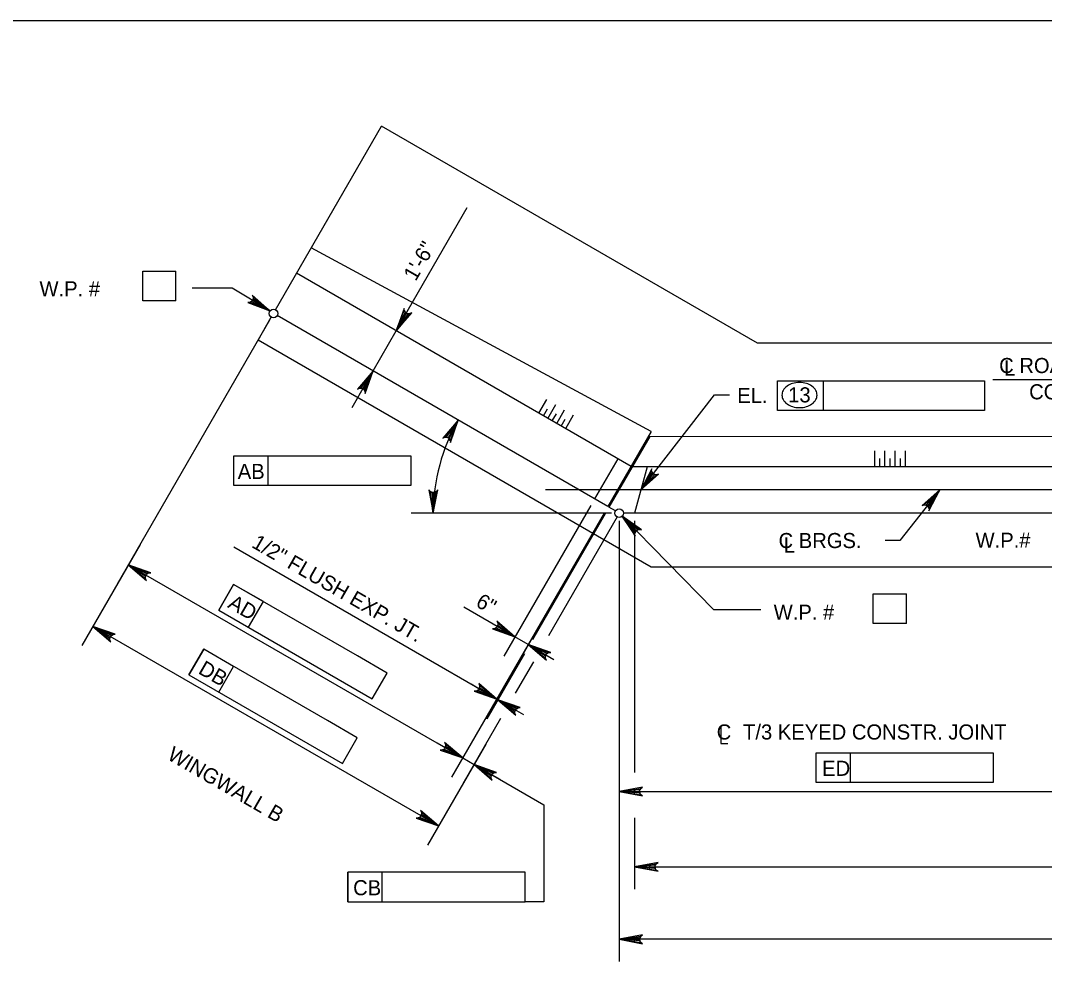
# Model space of a CAD drawing. Extents: x 638255 to 640306, y 296059 to 298435.
# Drawn here: x 638490.2 to 638693.7, y 297045.5 to 297232.5 of the extents above; entities that cross this region are included whole.
import ezdxf

# ---------------------------------------------------------------- set-up
doc = ezdxf.new("R2010")
doc.units = 0
for name, color, linetype in [('2', 7, 'Continuous'), ('Level 10', 7, 'Continuous'), ('Level 2', 7, 'Continuous'), ('Level 3', 7, 'Continuous')]:
    doc.layers.add(name, color=color, linetype=linetype)

msp = doc.modelspace()

# ---------------------------------------------------------------- linework, layer by layer
at = {"layer": '2'}
msp.add_line((638475.46, 297232.46), (639261.46, 297232.46), dxfattribs=at)
at = {"layer": 'Level 10'}
for p, q in [((638540.91, 297174.98), (638561.98, 297211.46)), ((638636.66, 297168.34), (638561.98, 297211.46)), ((638615.56, 297150.77), (638548, 297187.26)), ((638611.56, 297143.84), (638545.09, 297182.22)), ((638537.42, 297168.92), (638540.06, 297173.51)), ((638606.95, 297135.87), (638541.22, 297173.82)), ((638615.53, 297123.83), (638537.42, 297168.92)), ((638810.57, 297168.34), (638636.66, 297168.34)), ((638615.56, 297150.77), (638606.95, 297135.87)), ((638615.29, 297149.79), (638607.17, 297135.74)), ((638615.29, 297149.79), (638831.04, 297149.87)), ((638608.9, 297145.38), (638604.29, 297137.4)), ((638834.55, 297143.78), (638611.82, 297143.78)), ((638614.73, 297143.78), (638612.27, 297134.57)), ((638859.26, 297139.18), (638594.57, 297139.18)), ((638608.46, 297135), (638607.17, 297135.74)), ((638724.77, 297134.57), (638610.04, 297134.57)), ((638834.78, 297123.83), (638615.53, 297123.83))]:
    msp.add_line(p, q, dxfattribs=at)
at = {"layer": 'Level 2'}
for p, q in [((638593.24, 297154.42), (638594.82, 297157.15)), ((638594.13, 297153.91), (638594.94, 297155.31)), ((638595.01, 297153.39), (638596.59, 297156.12)), ((638596.79, 297152.37), (638598.36, 297155.1)), ((638595.9, 297152.88), (638596.71, 297154.28)), ((638597.67, 297151.86), (638598.48, 297153.26)), ((638598.56, 297151.35), (638600.13, 297154.08)), ((638659.97, 297143.78), (638659.97, 297146.94)), ((638662.02, 297143.78), (638662.02, 297146.94)), ((638664.06, 297143.78), (638664.06, 297146.94)), ((638666.11, 297143.78), (638666.11, 297146.94)), ((638660.99, 297143.78), (638660.99, 297145.4)), ((638663.04, 297143.78), (638663.04, 297145.4)), ((638665.09, 297143.78), (638665.09, 297145.4))]:
    msp.add_line(p, q, dxfattribs=at)
at = {"layer": 'Level 3'}
for p, q in [((638566.36, 297173.34), (638579, 297195.26)), ((638514.51, 297182.61), (638521.09, 297182.61)), ((638514.51, 297176.72), (638514.51, 297182.61)), ((638521.09, 297176.72), (638521.09, 297182.61)), ((638532.28, 297179.25), (638524.34, 297179.25)), ((638539.8, 297174.75), (638532.28, 297179.25)), ((638521.09, 297176.72), (638514.51, 297176.72)), ((638539.72, 297172.91), (638509.43, 297120.44)), ((638560.28, 297162.81), (638564.88, 297170.79)), ((638640.66, 297160.86), (638649.81, 297160.86)), ((638640.66, 297154.97), (638640.66, 297160.86)), ((638649.81, 297154.97), (638649.81, 297160.86)), ((638649.81, 297160.86), (638681.79, 297160.86)), ((638681.79, 297160.86), (638681.79, 297154.97)), ((638717.98, 297161.05), (638683.42, 297161.05)), ((638558.81, 297160.26), (638556.05, 297155.49)), ((638613.5, 297139.18), (638628.15, 297158.08)), ((638628.15, 297158.08), (638631.09, 297158.08)), ((638681.79, 297154.97), (638640.66, 297154.97)), ((638532.58, 297145.93), (638539.42, 297145.93)), ((638532.58, 297140.03), (638532.58, 297145.93)), ((638539.42, 297140.03), (638539.42, 297145.93)), ((638539.42, 297145.93), (638567.82, 297145.93)), ((638567.82, 297145.93), (638567.82, 297140.03)), ((638567.82, 297140.03), (638532.58, 297140.03)), ((638672.95, 297139.18), (638665, 297129.12)), ((638607.66, 297134.57), (638567.84, 297134.57)), ((638606.19, 297134.54), (638575.89, 297082.07)), ((638606.19, 297134.54), (638582.65, 297093.77)), ((638603.53, 297136.07), (638586.25, 297106.16)), ((638606.19, 297134.54), (638588.91, 297104.62)), ((638606.41, 297134.41), (638591.95, 297109.36)), ((638608.77, 297133.84), (638595.12, 297110.19)), ((638609.2, 297133.04), (638609.2, 297074.8)), ((638609.76, 297133.94), (638627.94, 297115.44)), ((638612.27, 297133.04), (638612.27, 297082.99)), ((638513.99, 297128.34), (638502.38, 297108.23)), ((638665, 297129.12), (638662.05, 297129.12)), ((638584.86, 297097.6), (638532.62, 297127.78)), ((638511.64, 297124.27), (638578.1, 297085.9)), ((638532.56, 297120.39), (638529.61, 297115.29)), ((638529.62, 297115.29), (638532.56, 297120.39)), ((638557.16, 297106.19), (638532.56, 297120.39)), ((638538.48, 297116.97), (638532.56, 297120.39)), ((638659.7, 297118.51), (638666.28, 297118.51)), ((638659.7, 297112.62), (638659.7, 297118.51)), ((638666.28, 297112.62), (638666.28, 297118.51)), ((638535.53, 297111.87), (638538.48, 297116.97)), ((638529.61, 297115.29), (638560.13, 297097.67)), ((638583.36, 297112.93), (638578.32, 297115.84)), ((638627.94, 297115.44), (638637.35, 297115.44)), ((638573.3, 297072.39), (638504.59, 297112.06)), ((638588.46, 297109.98), (638583.36, 297112.93)), ((638666.28, 297112.62), (638659.7, 297112.62)), ((638591.12, 297108.45), (638588.47, 297109.99)), ((638591.12, 297108.45), (638596.23, 297105.5)), ((638526.63, 297107.53), (638523.68, 297102.42)), ((638523.68, 297102.42), (638526.63, 297107.53)), ((638551.23, 297093.33), (638526.63, 297107.53)), ((638532.55, 297104.11), (638526.63, 297107.53)), ((638563.07, 297102.77), (638557.16, 297106.19)), ((638590.36, 297106.61), (638582.87, 297093.64)), ((638529.6, 297099.01), (638532.55, 297104.11)), ((638592.15, 297105.04), (638588.55, 297098.81)), ((638523.68, 297102.42), (638554.2, 297084.81)), ((638560.13, 297097.67), (638563.07, 297102.77)), ((638582.31, 297099.07), (638579.75, 297100.55)), ((638585.08, 297097.47), (638584.86, 297097.6)), ((638585.08, 297097.47), (638590.18, 297094.52)), ((638585.63, 297093.75), (638578.14, 297080.77)), ((638609.2, 297094.09), (638609.2, 297045.45)), ((638557.14, 297089.91), (638551.23, 297093.33)), ((638629.42, 297092.09), (638629.42, 297088.78)), ((638554.2, 297084.81), (638557.14, 297089.91)), ((638582.7, 297088.67), (638571.09, 297068.56)), ((638575.55, 297087.37), (638573, 297088.84)), ((638629.42, 297088.78), (638630.81, 297088.78)), ((638578.1, 297085.9), (638580.35, 297084.6)), ((638648.32, 297086.94), (638655.15, 297086.94)), ((638648.32, 297081.05), (638648.32, 297086.94)), ((638655.15, 297081.05), (638655.15, 297086.94)), ((638655.15, 297086.94), (638683.55, 297086.94)), ((638683.55, 297086.94), (638683.55, 297081.05)), ((638580.35, 297084.6), (638594.19, 297076.61)), ((638582.9, 297083.13), (638585.45, 297081.66)), ((638609.2, 297079.23), (638720.59, 297079.23)), ((638683.55, 297081.05), (638648.32, 297081.05)), ((638594.19, 297076.61), (638594.19, 297057.3)), ((638612.27, 297074.02), (638612.27, 297059.84)), ((638555.25, 297063.19), (638555.25, 297057.3)), ((638583.65, 297063.19), (638555.25, 297063.19)), ((638562.08, 297063.19), (638555.25, 297063.19)), ((638555.25, 297057.3), (638555.25, 297063.19)), ((638562.08, 297057.3), (638562.08, 297063.19)), ((638590.49, 297063.19), (638583.65, 297063.19)), ((638590.49, 297057.3), (638590.49, 297063.19)), ((638612.27, 297064.26), (638828.91, 297064.26)), ((638555.25, 297057.3), (638590.49, 297057.3)), ((638594.19, 297057.3), (638590.49, 297057.3)), ((638837.02, 297049.88), (638609.2, 297049.88))]:
    msp.add_line(p, q, dxfattribs=at)
for points in [[(638539.8, 297174.75), (638536.26, 297177.89), (638536.44, 297177.49), (638536.44, 297177.13), (638536.33, 297176.83), (638536.12, 297176.59), (638535.8, 297176.42), (638535.37, 297176.39), (638539.8, 297174.75), (638535.8, 297176.42), (638536.12, 297176.59), (638539.8, 297174.75), (638536.33, 297176.83), (638536.44, 297177.13), (638539.8, 297174.75), (638536.44, 297177.49)], [(638564.88, 297170.79), (638567.96, 297174.38), (638567.57, 297174.2), (638567.21, 297174.19), (638566.91, 297174.3), (638566.67, 297174.5), (638566.49, 297174.82), (638566.45, 297175.25), (638564.88, 297170.79), (638566.49, 297174.82), (638566.67, 297174.5), (638564.88, 297170.79), (638566.91, 297174.3), (638567.21, 297174.19), (638564.88, 297170.79), (638567.57, 297174.2)], [(638560.28, 297162.81), (638557.2, 297159.22), (638557.59, 297159.41), (638557.95, 297159.41), (638558.25, 297159.3), (638558.5, 297159.1), (638558.67, 297158.78), (638558.71, 297158.35), (638560.28, 297162.81), (638558.67, 297158.78), (638558.5, 297159.1), (638560.28, 297162.81), (638558.25, 297159.3), (638557.95, 297159.41), (638560.28, 297162.81), (638557.59, 297159.41)], [(638577.21, 297153.04), (638574.13, 297149.45), (638574.52, 297149.63), (638574.88, 297149.64), (638575.18, 297149.53), (638575.42, 297149.33), (638575.6, 297149.01), (638575.64, 297148.58), (638577.21, 297153.04), (638575.6, 297149.01), (638575.42, 297149.33), (638577.21, 297153.04), (638575.18, 297149.53), (638574.88, 297149.64), (638577.21, 297153.04), (638574.52, 297149.63)], [(638613.5, 297139.18), (638617.04, 297142.32), (638616.62, 297142.19), (638616.26, 297142.23), (638615.98, 297142.38), (638615.77, 297142.61), (638615.63, 297142.95), (638615.66, 297143.39), (638613.5, 297139.18), (638615.63, 297142.95), (638615.77, 297142.61), (638613.5, 297139.18), (638615.98, 297142.38), (638616.26, 297142.23), (638613.5, 297139.18), (638616.62, 297142.19)], [(638572.26, 297134.57), (638573.13, 297139.22), (638572.88, 297138.87), (638572.57, 297138.68), (638572.26, 297138.63), (638571.94, 297138.68), (638571.63, 297138.87), (638571.39, 297139.22), (638572.26, 297134.57), (638571.63, 297138.87), (638571.94, 297138.68), (638572.26, 297134.57), (638572.26, 297138.63), (638572.57, 297138.68), (638572.26, 297134.57), (638572.88, 297138.87)], [(638672.95, 297139.18), (638669.38, 297136.07), (638669.8, 297136.19), (638670.16, 297136.15), (638670.43, 297135.99), (638670.65, 297135.76), (638670.77, 297135.42), (638670.75, 297134.99), (638672.95, 297139.18), (638670.77, 297135.42), (638670.65, 297135.76), (638672.95, 297139.18), (638670.43, 297135.99), (638670.16, 297136.15), (638672.95, 297139.18), (638669.8, 297136.19)], [(638609.76, 297133.94), (638612.4, 297130.01), (638612.32, 297130.44), (638612.42, 297130.79), (638612.6, 297131.05), (638612.86, 297131.22), (638613.21, 297131.31), (638613.64, 297131.23), (638609.76, 297133.94), (638613.21, 297131.31), (638612.86, 297131.22), (638609.76, 297133.94), (638612.6, 297131.05), (638612.42, 297130.79), (638609.76, 297133.94), (638612.32, 297130.44)], [(638511.64, 297124.27), (638515.23, 297121.19), (638515.04, 297121.59), (638515.04, 297121.95), (638515.15, 297122.25), (638515.35, 297122.49), (638515.67, 297122.67), (638516.1, 297122.7), (638511.64, 297124.27), (638515.67, 297122.67), (638515.35, 297122.49), (638511.64, 297124.27), (638515.15, 297122.25), (638515.04, 297121.95), (638511.64, 297124.27), (638515.04, 297121.59)], [(638504.59, 297112.06), (638508.18, 297108.98), (638507.99, 297109.37), (638507.99, 297109.73), (638508.1, 297110.03), (638508.3, 297110.27), (638508.62, 297110.45), (638509.05, 297110.49), (638504.59, 297112.06), (638508.62, 297110.45), (638508.3, 297110.27), (638504.59, 297112.06), (638508.1, 297110.03), (638507.99, 297109.73), (638504.59, 297112.06), (638507.99, 297109.37)], [(638588.46, 297109.98), (638584.87, 297113.07), (638585.06, 297112.67), (638585.06, 297112.31), (638584.95, 297112.01), (638584.75, 297111.77), (638584.43, 297111.59), (638584, 297111.56), (638588.46, 297109.98), (638584.43, 297111.59), (638584.75, 297111.77), (638588.46, 297109.98), (638584.95, 297112.01), (638585.06, 297112.31), (638588.46, 297109.98), (638585.06, 297112.67)], [(638591.12, 297108.45), (638594.72, 297105.37), (638594.53, 297105.76), (638594.53, 297106.13), (638594.63, 297106.42), (638594.84, 297106.66), (638595.15, 297106.84), (638595.59, 297106.88), (638591.12, 297108.45), (638595.15, 297106.84), (638594.84, 297106.66), (638591.12, 297108.45), (638594.63, 297106.42), (638594.53, 297106.13), (638591.12, 297108.45), (638594.53, 297105.76)], [(638584.86, 297097.6), (638581.27, 297100.68), (638581.45, 297100.29), (638581.46, 297099.92), (638581.35, 297099.63), (638581.14, 297099.38), (638580.83, 297099.2), (638580.39, 297099.17), (638584.86, 297097.6), (638580.83, 297099.2), (638581.14, 297099.38), (638584.86, 297097.6), (638581.35, 297099.63), (638581.46, 297099.92), (638584.86, 297097.6), (638581.45, 297100.29)], [(638585.08, 297097.47), (638588.67, 297094.39), (638588.49, 297094.78), (638588.48, 297095.15), (638588.59, 297095.44), (638588.79, 297095.69), (638589.11, 297095.86), (638589.54, 297095.9), (638585.08, 297097.47), (638589.11, 297095.86), (638588.79, 297095.69), (638585.08, 297097.47), (638588.59, 297095.44), (638588.48, 297095.15), (638585.08, 297097.47), (638588.49, 297094.78)], [(638578.1, 297085.9), (638574.51, 297088.98), (638574.7, 297088.58), (638574.7, 297088.22), (638574.59, 297087.93), (638574.39, 297087.68), (638574.07, 297087.5), (638573.64, 297087.47), (638578.1, 297085.9), (638574.07, 297087.5), (638574.39, 297087.68), (638578.1, 297085.9), (638574.59, 297087.93), (638574.7, 297088.22), (638578.1, 297085.9), (638574.7, 297088.58)], [(638580.35, 297084.6), (638583.94, 297081.52), (638583.75, 297081.92), (638583.75, 297082.28), (638583.86, 297082.58), (638584.06, 297082.82), (638584.38, 297083), (638584.81, 297083.03), (638580.35, 297084.6), (638584.38, 297083), (638584.06, 297082.82), (638580.35, 297084.6), (638583.86, 297082.58), (638583.75, 297082.28), (638580.35, 297084.6), (638583.75, 297081.92)], [(638609.2, 297079.23), (638613.85, 297078.35), (638613.49, 297078.6), (638613.31, 297078.91), (638613.25, 297079.23), (638613.31, 297079.54), (638613.49, 297079.85), (638613.85, 297080.1), (638609.2, 297079.23), (638613.49, 297079.85), (638613.31, 297079.54), (638609.2, 297079.23), (638613.25, 297079.23), (638613.31, 297078.91), (638609.2, 297079.23), (638613.49, 297078.6)], [(638573.3, 297072.39), (638569.7, 297075.47), (638569.89, 297075.08), (638569.89, 297074.71), (638569.78, 297074.42), (638569.58, 297074.17), (638569.27, 297073.99), (638568.83, 297073.96), (638573.3, 297072.39), (638569.27, 297073.99), (638569.58, 297074.17), (638573.3, 297072.39), (638569.78, 297074.42), (638569.89, 297074.71), (638573.3, 297072.39), (638569.89, 297075.08)], [(638612.27, 297064.26), (638616.92, 297063.39), (638616.56, 297063.64), (638616.37, 297063.95), (638616.32, 297064.26), (638616.37, 297064.57), (638616.56, 297064.89), (638616.92, 297065.13), (638612.27, 297064.26), (638616.56, 297064.89), (638616.37, 297064.57), (638612.27, 297064.26), (638616.32, 297064.26), (638616.37, 297063.95), (638612.27, 297064.26), (638616.56, 297063.64)], [(638609.2, 297049.88), (638613.85, 297049), (638613.49, 297049.25), (638613.31, 297049.56), (638613.25, 297049.88), (638613.31, 297050.19), (638613.49, 297050.5), (638613.85, 297050.75), (638609.2, 297049.88), (638613.49, 297050.5), (638613.31, 297050.19), (638609.2, 297049.88), (638613.25, 297049.88), (638613.31, 297049.56), (638609.2, 297049.88), (638613.49, 297049.25)]]:
    msp.add_lwpolyline(points, dxfattribs=at)
for points in [[(638537.02, 297175.84), (638537.53, 297176.68), (638539.8, 297174.75)], [(638565.93, 297173.59), (638566.78, 297173.1), (638564.88, 297170.79)], [(638558.38, 297160.51), (638559.23, 297160.02), (638560.28, 297162.81)], [(638615.69, 297141.21), (638614.92, 297141.81), (638613.5, 297139.18)], [(638670.73, 297137.17), (638671.5, 297136.56), (638672.95, 297139.18)], [(638612.17, 297132.18), (638611.47, 297131.49), (638609.76, 297133.94)], [(638514.44, 297123.22), (638513.94, 297122.37), (638511.64, 297124.27)], [(638507.38, 297111.01), (638506.89, 297110.16), (638504.59, 297112.06)], [(638586.16, 297111.88), (638585.67, 297111.03), (638588.47, 297109.99)], [(638593.92, 297107.4), (638593.43, 297106.55), (638591.12, 297108.45)], [(638582.55, 297099.5), (638582.06, 297098.65), (638584.86, 297097.6)], [(638587.88, 297096.42), (638587.39, 297095.57), (638585.08, 297097.47)], [(638575.8, 297087.8), (638575.3, 297086.95), (638578.1, 297085.9)], [(638583.14, 297083.55), (638582.65, 297082.7), (638580.35, 297084.6)], [(638612.14, 297079.72), (638612.14, 297078.73), (638609.2, 297079.23)], [(638570.99, 297074.29), (638570.5, 297073.44), (638573.3, 297072.39)], [(638615.21, 297064.75), (638615.21, 297063.77), (638612.27, 297064.26)], [(638612.14, 297050.37), (638612.14, 297049.38), (638609.2, 297049.88)]]:
    msp.add_lwpolyline(points, close=True, dxfattribs=at)
for centre in [(638540.49, 297174.24), (638609.2, 297134.57)]:
    msp.add_circle(centre, 0.849, dxfattribs=at)
for centre, radius, start, end in [((638643.36, 297158.02), 1.82, 149.9767, 180), ((638644.16, 297157.56), 2.75, 125.6316, 149.9767), ((638644.69, 297156.82), 3.65, 106.5358, 125.6316), ((638645.03, 297155.67), 4.86, 90, 106.5358), ((638645.03, 297155.67), 4.86, 73.4642, 90), ((638645.37, 297156.82), 3.65, 54.3684, 73.4642), ((638645.9, 297157.56), 2.75, 30.0233, 54.3684), ((638646.7, 297158.02), 1.82, 0, 30.0233), ((638643.36, 297158.02), 1.82, 180, 210.0233), ((638644.16, 297158.49), 2.75, 210.0233, 234.3684), ((638645.9, 297158.49), 2.75, 305.6316, 329.9767), ((638646.7, 297158.02), 1.82, 329.9767, 0), ((638644.69, 297159.22), 3.65, 234.3684, 253.4642), ((638645.03, 297160.38), 4.86, 253.4642, 270), ((638645.03, 297160.38), 4.86, 270, 286.5358), ((638645.37, 297159.22), 3.65, 286.5358, 305.6316), ((638609.2, 297134.57), 36.94, 149.9994, 179.9989)]:
    msp.add_arc(centre, radius, start, end, dxfattribs=at)

# ---------------------------------------------------------------- texts
for s, height, rotation, p in [('1\'-6"', 3, 60, (638568.75, 297180.49)), ('1/2" FLUSH EXP. JT.', 3.0001, 330, (638535.96, 297127.89)), ('AD', 3, 330, (638531.22, 297115.92)), ('6"', 3, 330, (638580.48, 297116.17)), ('DB', 3, 330, (638525.35, 297102.81)), ('WINGWALL B', 3, 330, (638519.18, 297085.76))]:
    msp.add_text(s, height=height, rotation=rotation, dxfattribs=at).set_placement(p)
for s, height, p in [('W.P. #', 3, (638493.99, 297177.64)), ('C ROADWAY &', 3.0001, (638684.71, 297162.39)), ('L', 3, (638685.67, 297161.9)), ('EL.', 3, (638632.66, 297156.45)), ('13', 3, (638642.78, 297156.56)), ('CONSTR. B', 3, (638690.67, 297157.17)), ('AB', 3, (638533.39, 297141.35)), ('C BRGS.', 3, (638640.87, 297127.61)), ('W.P.#', 3, (638680.02, 297127.67)), ('L', 3, (638641.89, 297126.73)), ('W.P. #', 3, (638639.9, 297113.36)), ('C', 3, (638628.58, 297089.57)), ('T/3 KEYED CONSTR. JOINT', 3.0001, (638633.81, 297089.57)), ('ED', 3, (638649.53, 297082.35)), ('CB', 3, (638556.32, 297058.62))]:
    msp.add_text(s, height=height, dxfattribs=at).set_placement(p)

doc.saveas('drawing.dxf')
